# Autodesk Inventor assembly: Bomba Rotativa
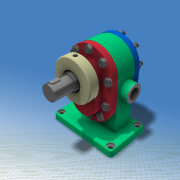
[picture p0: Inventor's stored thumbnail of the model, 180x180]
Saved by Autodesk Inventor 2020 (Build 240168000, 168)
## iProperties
Created: 2013-11
Part Number: Bomba Rotativa
Document SubType Name: Assembly
Designer: normanpa
Author: normanpa
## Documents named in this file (11)
- C:\Users\Miguel2\Desktop\Bomba Rotativa\Workspace\ENU\552100320579484105\TutorialModelPath\Bomba Rotativa.iam
- C:\Users\Miguel2\Desktop\Bomba Rotativa\Workspace\ENU\552100320579484105\TutorialModelPath\Pump_Components\Pump Base.ipt
- C:\Users\Miguel2\Desktop\Bomba Rotativa\Workspace\ENU\552100320579484105\TutorialModelPath\Pump_Components\Pump_Back_Cover.ipt
- C:\Users\Miguel2\Desktop\Bomba Rotativa\Workspace\ENU\552100320579484105\TutorialModelPath\Pump_Components\Pump_Front_Cover.ipt
- C:\Users\Miguel2\Desktop\Bomba Rotativa\Workspace\ENU\552100320579484105\TutorialModelPath\Pump_Components\Lock_Ring.ipt
- C:\Users\Miguel2\Desktop\Bomba Rotativa\Workspace\ENU\552100320579484105\TutorialModelPath\Pump_Components\Drive_Shaft.ipt
- C:\Users\Miguel2\Desktop\Bomba Rotativa\Workspace\ENU\552100320579484105\TutorialModelPath\Pump_Components\Driven_Shaft_Gear.ipt
- C:\Users\Miguel2\Desktop\Bomba Rotativa\Workspace\ENU\552100320579484105\TutorialModelPath\Pump_Components\ISO 2491 - A  10 x 6 x 22.ipt
- C:\Users\Miguel2\Desktop\Bomba Rotativa\Workspace\ENU\552100320579484105\TutorialModelPath\Pump_Components\Packing_2.ipt
- C:\Users\Miguel2\Desktop\Bomba Rotativa\Workspace\ENU\552100320579484105\TutorialModelPath\Pump_Components\Packing_1.ipt
- C:\Users\Miguel2\Desktop\Bomba Rotativa\Workspace\ENU\552100320579484105\TutorialModelPath\Pump_Components\BoltedConnection.iam
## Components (22 placed, 10 different names)
1. Pump Base:1 — Rigid:1, Rigid:2, Angle:1
2. Pump_Back_Cover:1 — Rigid:2, Rotational:1, Rotational:2
3. Pump_Front_Cover:1 — Rigid:1, Rigid:3, Rigid:5, Rigid:6
4. Lock_Ring:1 — Rigid:3
5. Drive_Shaft:1 — Rotational:1, Rigid:4, Rotational:3, Angle:1
6. Driven_Shaft — Rotational:2
7. ISO 2491 A A  10 x 6 x 22:1 — Rigid:4
8. Packing_2:1 — Rotational:3, Rotational:4
9. Packing_1:1 — Rotational:4, Rotational:5
10. Packing_1:2 — Rotational:5, Rotational:6
11. Packing_1:3 — Rotational:6, Rotational:7
12. Packing_2:2 — Rotational:7
13. BoltedConnection:1 [sub-assembly] — Rigid:5
14. BoltedConnection:2 [sub-assembly]
15. BoltedConnection:3 [sub-assembly]
16. BoltedConnection:4 [sub-assembly]
17. BoltedConnection:5 [sub-assembly]
18. BoltedConnection:6 [sub-assembly] — Rigid:6
19. BoltedConnection:7 [sub-assembly]
20. BoltedConnection:8 [sub-assembly]
21. BoltedConnection:9 [sub-assembly]
22. BoltedConnection:10 [sub-assembly]
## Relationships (14: RevoluteJoint 7, WeldJoint 6, Angle 1)
- Rigid:1 [WeldJoint]: Pump Base:1 ↔ Pump_Front_Cover:1
- Rigid:2 [WeldJoint]: Pump Base:1 ↔ Pump_Back_Cover:1
- Rigid:3 [WeldJoint]: Pump_Front_Cover:1 ↔ Lock_Ring:1
- Rotational:1 [RevoluteJoint]: Pump_Back_Cover:1 ↔ Drive_Shaft:1
- Rotational:2 [RevoluteJoint]: Pump_Back_Cover:1 ↔ Driven_Shaft
- Rigid:4 [WeldJoint]: Drive_Shaft:1 ↔ ISO 2491 A A  10 x 6 x 22:1
- Rotational:3 [RevoluteJoint]: Drive_Shaft:1 ↔ Packing_2:1
- Rotational:4 [RevoluteJoint]: Packing_2:1 ↔ Packing_1:1
- Rotational:5 [RevoluteJoint]: Packing_1:1 ↔ Packing_1:2
- Rotational:6 [RevoluteJoint]: Packing_1:2 ↔ Packing_1:3
- Rotational:7 [RevoluteJoint]: Packing_1:3 ↔ Packing_2:2
- Angle:1: Pump Base:1 ↔ Drive_Shaft:1
- Rigid:5 [WeldJoint]: Pump_Front_Cover:1 ↔ BoltedConnection:1
- Rigid:6 [WeldJoint]: Pump_Front_Cover:1 ↔ BoltedConnection:6
